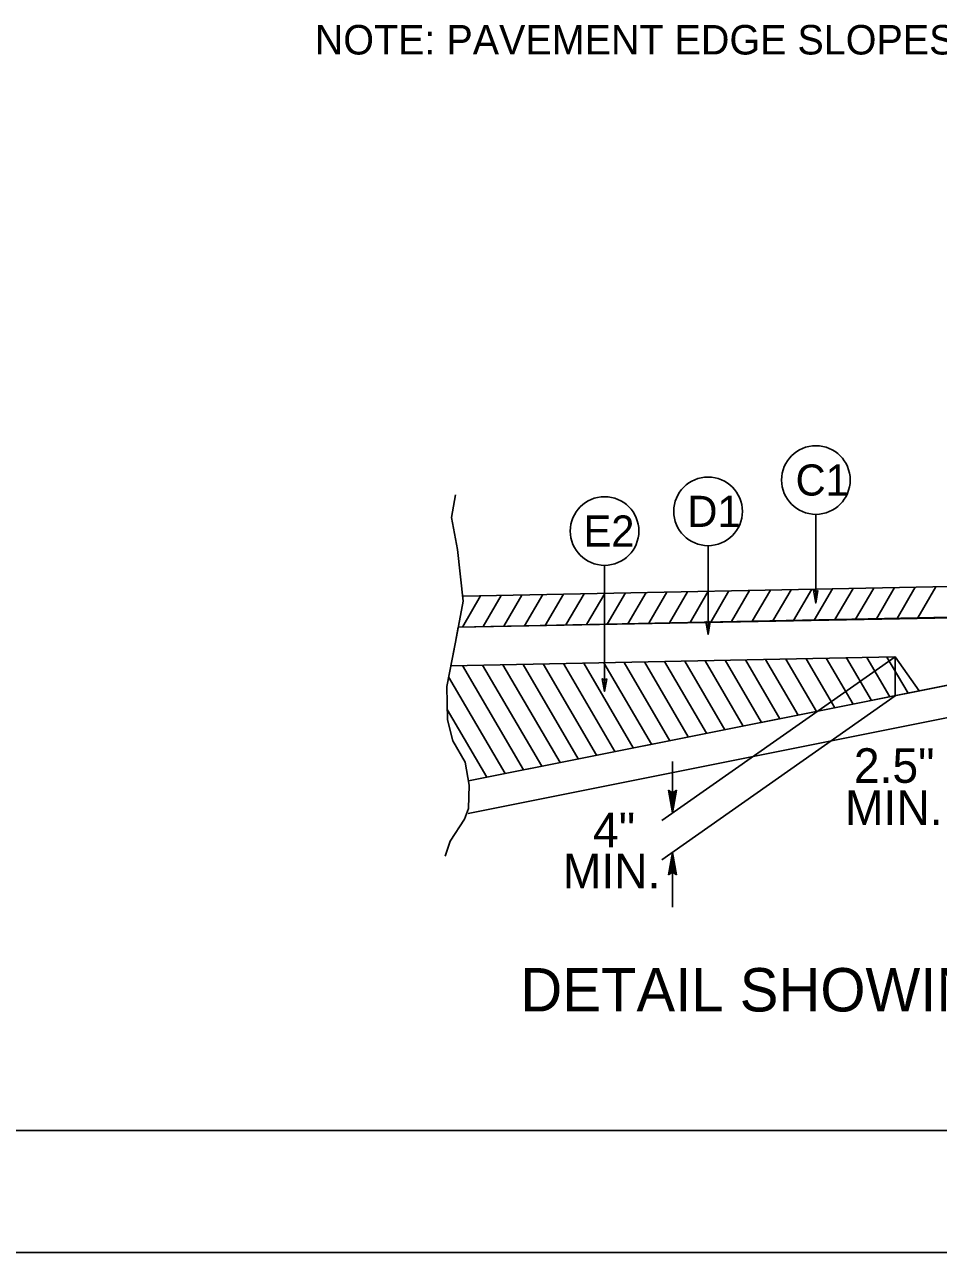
# Model space of a CAD drawing. Extents: x 1553884 to 1554215, y 810431 to 810779.
# Drawn here: x 1554073.08 to 1554098.35, y 810614.43 to 810648.38 of the extents above; entities that cross this region are included whole.
import ezdxf

# ---------------------------------------------------------------- set-up
doc = ezdxf.new("R2010")
doc.units = 0
for name, color, linetype in [('Old_Level_2', 7, 'Continuous'), ('Old_Level_20', 7, 'Continuous'), ('Prop CMT Steel Beam Girder', 7, 'Continuous'), ('Prop Dimension', 7, 'Continuous'), ('Prop Lane Arrow CELL', 7, 'Continuous'), ('Prop Terminator CELL', 7, 'Continuous'), ('Typical Detail Pavement Repair CELL', 7, 'Continuous')]:
    doc.layers.add(name, color=color, linetype=linetype)

msp = doc.modelspace()

# ---------------------------------------------------------------- linework, layer by layer
at = {"layer": 'Old_Level_2'}
msp.add_line((1553906.821, 810617.805), (1554154.321, 810617.805), dxfattribs=at)
at = {"layer": 'Old_Level_20'}
for p, q in [((1554094.956, 810634.841), (1554094.956, 810632.388)), ((1554091.978, 810633.974), (1554091.978, 810631.521)), ((1554089.116, 810633.43), (1554089.116, 810629.942)), ((1554106.445, 810633.001), (1554085.194, 810632.576)), ((1554091.983, 810632.712), (1554091.479, 810631.85)), ((1554092.555, 810632.723), (1554092.052, 810631.862)), ((1554093.127, 810632.734), (1554092.624, 810631.873)), ((1554093.699, 810632.746), (1554093.196, 810631.885)), ((1554094.272, 810632.757), (1554093.769, 810631.896)), ((1554094.844, 810632.769), (1554094.341, 810631.907)), ((1554095.416, 810632.78), (1554094.913, 810631.919)), ((1554095.988, 810632.792), (1554095.485, 810631.93)), ((1554096.56, 810632.803), (1554096.057, 810631.942)), ((1554097.132, 810632.815), (1554096.629, 810631.953)), ((1554097.705, 810632.826), (1554097.202, 810631.964)), ((1554098.277, 810632.837), (1554097.774, 810631.976)), ((1554085.689, 810632.586), (1554085.186, 810631.724)), ((1554086.261, 810632.597), (1554085.757, 810631.736)), ((1554086.833, 810632.609), (1554086.33, 810631.747)), ((1554087.405, 810632.62), (1554086.902, 810631.759)), ((1554087.977, 810632.631), (1554087.474, 810631.77)), ((1554088.55, 810632.643), (1554088.046, 810631.782)), ((1554089.122, 810632.654), (1554088.619, 810631.793)), ((1554089.694, 810632.666), (1554089.191, 810631.805)), ((1554090.266, 810632.677), (1554089.763, 810631.816)), ((1554090.839, 810632.689), (1554090.335, 810631.828)), ((1554091.411, 810632.7), (1554090.907, 810631.839)), ((1554104.581, 810632.112), (1554085.073, 810631.722)), ((1554106.477, 810631.694), (1554085.354, 810627.468)), ((1554097.149, 810630.898), (1554084.866, 810630.652)), ((1554106.437, 810630.785), (1554085.346, 810626.566)), ((1554086.303, 810630.681), (1554087.884, 810627.974)), ((1554086.862, 810630.692), (1554088.39, 810628.076)), ((1554087.421, 810630.703), (1554088.896, 810628.177)), ((1554087.98, 810630.714), (1554089.403, 810628.279)), ((1554088.539, 810630.725), (1554089.909, 810628.38)), ((1554089.098, 810630.737), (1554090.416, 810628.481)), ((1554089.657, 810630.748), (1554090.922, 810628.582)), ((1554090.216, 810630.759), (1554091.428, 810628.684)), ((1554097.149, 810630.898), (1554090.696, 810626.379)), ((1554090.775, 810630.77), (1554091.935, 810628.785)), ((1554091.334, 810630.782), (1554092.441, 810628.886)), ((1554091.893, 810630.793), (1554092.947, 810628.987)), ((1554092.451, 810630.804), (1554093.453, 810629.089)), ((1554093.01, 810630.815), (1554093.96, 810629.19)), ((1554093.569, 810630.826), (1554094.466, 810629.291)), ((1554094.128, 810630.838), (1554094.972, 810629.393)), ((1554094.687, 810630.849), (1554095.479, 810629.494)), ((1554095.246, 810630.86), (1554095.985, 810629.595)), ((1554095.805, 810630.871), (1554096.491, 810629.696)), ((1554096.364, 810630.882), (1554096.998, 810629.798)), ((1554096.923, 810630.893), (1554097.504, 810629.899)), ((1554097.815, 810629.961), (1554097.149, 810630.898)), ((1554097.149, 810630.898), (1554097.149, 810629.826)), ((1554084.804, 810630.343), (1554086.365, 810627.671)), ((1554085.185, 810630.658), (1554086.871, 810627.772)), ((1554085.744, 810630.67), (1554087.378, 810627.873)), ((1554097.149, 810629.826), (1554090.696, 810625.285)), ((1554097.815, 810629.961), (1554095.01, 810629.4)), ((1554084.765, 810629.441), (1554085.859, 810627.569)), ((1554095.01, 810629.4), (1554085.354, 810627.468)), ((1554090.995, 810628.007), (1554090.995, 810626.588)), ((1554090.995, 810626.588), (1554090.883, 810627.213)), ((1554090.995, 810627.131), (1554090.883, 810627.213)), ((1554090.995, 810626.588), (1554090.899, 810627.201)), ((1554090.916, 810627.189), (1554090.995, 810626.588)), ((1554090.995, 810626.588), (1554090.932, 810627.177)), ((1554090.948, 810627.167), (1554090.995, 810626.588)), ((1554090.995, 810626.588), (1554090.963, 810627.155)), ((1554090.979, 810627.143), (1554090.995, 810626.588)), ((1554090.995, 810626.588), (1554091.104, 810627.213)), ((1554091.104, 810627.213), (1554090.995, 810627.131)), ((1554091.088, 810627.201), (1554090.995, 810626.588)), ((1554090.995, 810626.588), (1554091.073, 810627.189)), ((1554091.057, 810627.177), (1554090.995, 810626.588)), ((1554090.995, 810626.588), (1554091.041, 810627.167)), ((1554091.026, 810627.155), (1554090.995, 810626.588)), ((1554090.995, 810626.588), (1554091.01, 810627.143)), ((1554090.995, 810627.131), (1554090.995, 810626.588)), ((1554090.995, 810625.493), (1554090.883, 810624.868)), ((1554090.901, 810624.879), (1554090.995, 810625.493)), ((1554090.995, 810625.493), (1554090.916, 810624.891)), ((1554090.932, 810624.903), (1554090.995, 810625.493)), ((1554090.995, 810625.493), (1554090.948, 810624.914)), ((1554090.963, 810624.925), (1554090.995, 810625.493)), ((1554090.995, 810625.493), (1554090.979, 810624.937)), ((1554090.995, 810625.493), (1554090.995, 810623.974)), ((1554090.995, 810625.493), (1554091.104, 810624.868)), ((1554090.995, 810624.949), (1554090.995, 810625.493)), ((1554091.01, 810624.937), (1554090.995, 810625.493)), ((1554090.995, 810625.493), (1554091.026, 810624.925)), ((1554091.041, 810624.914), (1554090.995, 810625.493)), ((1554090.995, 810625.493), (1554091.057, 810624.903)), ((1554091.073, 810624.891), (1554090.995, 810625.493)), ((1554090.995, 810625.493), (1554091.088, 810624.879)), ((1554090.883, 810624.868), (1554090.995, 810624.949)), ((1554090.995, 810624.949), (1554091.104, 810624.868))]:
    msp.add_line(p, q, dxfattribs=at)
msp.add_lwpolyline([(1554084.997, 810635.381), (1554084.883, 810634.758), (1554085.053, 810633.873), (1554085.204, 810632.44), (1554084.997, 810631.309), (1554084.752, 810630.084), (1554084.771, 810629.16), (1554084.921, 810628.576), (1554085.261, 810627.991), (1554085.374, 810627.35), (1554085.355, 810626.71), (1554085.242, 810626.408), (1554084.846, 810625.804), (1554084.714, 810625.389)], dxfattribs=at)
for centre in [(1554094.957, 810635.79), (1554091.978, 810634.923), (1554089.115, 810634.379)]:
    msp.add_circle(centre, 0.949, dxfattribs=at)
at = {"layer": 'Prop CMT Steel Beam Girder'}
for points in [[(1554095.016, 810632.739), (1554094.956, 810632.388), (1554094.893, 810632.741), (1554094.956, 810632.696)], [(1554092.039, 810631.873), (1554091.978, 810631.521), (1554091.916, 810631.875), (1554091.978, 810631.83)], [(1554089.176, 810630.294), (1554089.116, 810629.942), (1554089.053, 810630.296), (1554089.116, 810630.251)]]:
    msp.add_lwpolyline(points, close=True, dxfattribs=at)
at = {"layer": 'Prop Lane Arrow CELL'}
msp.add_line((1553901.353, 810614.43), (1554156.35, 810614.43), dxfattribs=at)
at = {"layer": 'Prop Terminator CELL'}
msp.add_lwpolyline([(1554104.581, 810632.089), (1554085.073, 810631.722), (1554084.997, 810631.309), (1554084.866, 810630.652), (1554097.149, 810630.898), (1554097.815, 810629.961), (1554105.059, 810631.41)], close=True, dxfattribs=at)

# ---------------------------------------------------------------- texts
at = {"layer": 'Old_Level_20'}
for s, height, p in [('2.5"', 0.9558, (1554096.007, 810627.416)), ('MIN.', 0.9558, (1554095.763, 810626.253)), ('4"', 0.9558, (1554088.798, 810625.637)), ('MIN.', 0.9558, (1554087.962, 810624.499)), ('DETAIL SHOWING METHOD OF WEDGING NO. 1', 1.2, (1554086.788, 810621.094))]:
    msp.add_text(s, height=height, dxfattribs=at).set_placement(p)
at = {"layer": 'Prop Dimension'}
msp.add_text('NOTE: PAVEMENT EDGE SLOPES ARE 1:1 UNLESS SHOWN OTHERWISE.', height=0.81625, dxfattribs=at).set_placement((1554081.105, 810647.557))
at = {"layer": 'Typical Detail Pavement Repair CELL'}
for s, p in [('C1', (1554094.396, 810635.36)), ('D1', (1554091.405, 810634.493)), ('E2', (1554088.534, 810633.949))]:
    msp.add_text(s, height=0.8608, dxfattribs=at).set_placement(p)

doc.saveas('drawing.dxf')
